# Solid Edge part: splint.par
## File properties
Author: Mac
Template: Normal.par
Last saved by: Mac
Revision: 3
Application: Solid Edge
Material: Stainless steel
Face Style: Steel
Fill Style: ANSI32(Steel)
Virtual Style: Stainless steel
Coef. of Thermal Exp: 1.6e-05
Thermal Conductivity: 17.0
Specific Heat: 502.0
Modulus of Elasticity: 193053196000.0
Poission's Ratio: 0.29
Yield Stress: 310264065.0
Ultimate Stress: 641212401.0
Elongation: 0.0
Density: 7750,000 kg/m^3
Accuracy: 0,990
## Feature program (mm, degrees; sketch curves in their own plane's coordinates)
swept protrusion "unnamed SweptProtrusion 1"
swept protrusion "SweptProtrusion_20"
swept protrusion "SweptProtrusion_22"  Profile_54_CrossSections_Plane1_FractionOfCurve = 1
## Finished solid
Body 1: solid body, 12 faces, 11 edges, 0 vertices.
  Faces by surface: torus 7, cylinder 3, plane 2
  Edges by curve: circle 11
Bounding box of the edges (mm; curved faces can reach further): 0.146 x 0.018 x 0.668, from (-0.0091, -0.0091, -0.413) to (0.1373, 0.0091, 0.2546).
Cylindrical faces by radius (mm): R0.0091 x3
Toroidal faces (ring radius, tube radius in mm): R0.0259 r0.0091 x1, R0.0288 r0.0091 x1, R0.034 r0.0091 x1, R0.0349 r0.0091 x1, R0.0681 r0.0091 x1, R0.0896 r0.0091 x1, R0.0917 r0.0091 x1
Planar faces by outward normal: -z 1, oblique 1
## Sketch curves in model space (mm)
line (0.0739, 0, -0.1134) -> (0.1081, 0, -0.2152)
arc centre (0.0985, 0, -0.1052) radius 0.0259 from (0.0739, 0, -0.0969) through (0.0726, 0, -0.1052) to (0.0739, 0, -0.1134)
arc centre (-0.011, 0, -0.0682) radius 0.0896 from (0.0739, 0, -0.0396) through (0.0786, 0, -0.0682) to (0.0739, 0, -0.0969)
arc centre (0.1062, 0, -0.0287) radius 0.034 from (0.0739, 0, -0.0178) through (0.0721, 0, -0.0287) to (0.0739, 0, -0.0396)
arc centre (-0.013, 0, 0.0116) radius 0.0917 from (0.0739, 0, 0.0409) through (0.0787, 0, 0.0116) to (0.0739, 0, -0.0178)
arc centre (0.107, 0, 0.0521) radius 0.0349 from (0.0739, 0, 0.0633) through (0.0721, 0, 0.0521) to (0.0739, 0, 0.0409)
line (0.0739, 0, 0.0633) -> (0.1287, 0, 0.2254)
arc centre (0.1014, 0, 0.2346) radius 0.0288 from (0.1259, 0, 0.2498) through (0.13, 0, 0.2379) to (0.1287, 0, 0.2254)
arc centre (0.068, 0, 0.2139) radius 0.0681 from (0.1259, 0, 0.2498) through (0.0462, 0, 0.2783) to (0, 0, 0.2113)
line (0, 0, 0.2113) -> (0, 0, -0.413)
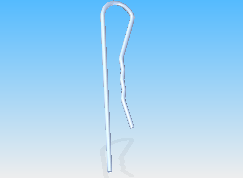
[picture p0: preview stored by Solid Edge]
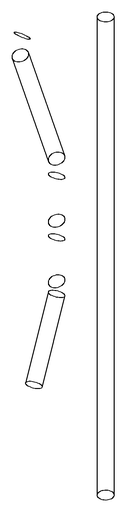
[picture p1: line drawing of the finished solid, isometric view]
